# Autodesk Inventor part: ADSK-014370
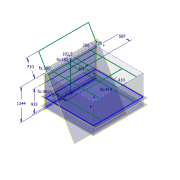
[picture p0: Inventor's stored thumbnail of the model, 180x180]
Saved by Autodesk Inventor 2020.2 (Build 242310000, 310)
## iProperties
Created: 2019-10
Part Number: ADSK-014370
Material: 1.0501 C35
Document SubType Name: Modeling
Designer: lutzd
Mass: 4.35255e+07 g
Surface Area: 194822 cm^2
Volume: 5.55173e+06 cm^3
Density: 7.84 g/cm^3
Appearance: Klar
VLDS_Profile: Default Part
VLDS_TimeStamp: 2016-07-29
VLDS_FailCnt: 0
VLDS_AcceptCnt: 0
Dimensions: 2170x1230x2080 mm
Mass: 43525,548 kg
DocNumber: ADSK-014370
Folder: 01 - Themengebiete\Simplification\01 - Packaging machine\Parts\
VDS_Category: 3D Komponenten
VDS_NumSchm: Autodesk
VLT_Material: 1.0501 C35
Title: skeleton
Author: lutzd
Revision Number: -
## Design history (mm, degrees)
sketch "Skizze1"
  geometry: L1 (-1040, -1085)-(1040, -1085); L2 (1040, -1085)-(1040, 1085); L3 (1040, 1085)-(-1040, 1085); L4 (-1040, 1085)-(-1040, -1085); L5 (-1040, -1085)-(1040, 1085); L6 (1040, -1085)-(-1040, 1085); 1 further point
  constraints: 12 end point, 2 midpoint, 2 parallel, 1 horizontal, 1 perpendicular
  dimensions: "d0" = 2080 distance of L3.end L2.end; "d1" = 2170 distance of L2.end L1.end
extrude "Extrusion1" new body sketch "Skizze1" distance "d2" = 1230; taper "d3" = 0 deg
workplane "Arbeitsebene1"
sketch "Skizze2"
  geometry: L1 (1040, -1085)-(-1040, -1085) reference; L2 (-1040, 1085)-(1040, 1085) reference; L3 (1040, -704)-(-1040, -704); L4 (1040, 704)-(-1040, 704); L5 (1040, 1085)-(1040, -1085) reference; L6 (-1040, -1085)-(-1040, 1085) reference; 1 further point
  constraints: 4 end point, 4 vertical alignment, 2 horizontal
  dimensions: "d5" = 381 distance between parallel lines of L2 L4; "d6" = 381 distance between parallel lines of L1 L3 (= d5)
sketch "Skizze3"
  geometry: L1 (-970, -805)-(1040, -805); L2 (-970, 805)-(1040, 805); L3 (1040, 1085)-(-1040, 1085) reference; L4 (-1040, 1085)-(-1040, -1085) reference; L5 (-1040, -1085)-(1040, -1085) reference; L6 (1040, -1085)-(1040, 1085) reference; L7 (-970, 1085)-(-970, -1085); L8 (-970, 0)-(1040, 0); L9 (-460, -805)-(-460, 0); L10 (-460, 0)-(-460, 805); L11 (-970, 182.5)-(-460, 182.5); L12 (-970, -182.5)-(-460, -182.5); L13 (1040, 182.5)-(630, 182.5); L14 (1040, -182.5)-(630, -182.5); L15 (405, -805)-(405, 0); L16 (405, 0)-(405, 805); 1 further point
  constraints: 24 end point, 20 point on line, 4 horizontal, 4 perpendicular, 2 collinear, 2 midpoint, 1 vertical
  dimensions: "d7" = 280 distance between parallel lines of L3 L2; "d8" = 280 distance between parallel lines of L5 L1 (= d7); "d9" = 70 distance between parallel lines of L4 L7; "d10" = 510 distance between parallel lines of L7 L10; "d11" = 182.5 distance between parallel lines of L8 L11; "d12" = 182.5 distance between parallel lines of L8 L12 (= d11); "d13" = 410 distance of L13.start L13.end; "d14" = 410 distance of L14.start L14.end (= d13); "d15" = 865 distance between parallel lines of L9 L15
workplane "Arbeitsebene3"
sketch "Skizze4"
  geometry: L1 (0, 2170)-(0, 0) reference; L2 (1344, 2170)-(1344, 0); 1 further point
  constraints: 2 end point, 2 horizontal alignment, 1 vertical
  dimensions: "d16" = 1344 distance between parallel lines of L1 L2
workplane "Arbeitsebene2"
sketch "Skizze5"
  geometry: L1 (0, 0)-(2170, 0) reference; L2 (2170, 0)-(2170, 710); L3 (2170, 710)-(0, 710); L4 (0, 710)-(0, 0); 1 further point
  constraints: 6 end point, 2 perpendicular, 1 vertical
  dimensions: "d18" = 710 distance of L1.end L2.end
sketch "Skizze6"
  geometry: L1 (0, 1085)-(1230, 1085); L2 (935, 2170)-(935, 1085); L3 (935, 1085)-(935, 0); L4 (0, 2170)-(0, 0) reference; 2 further points
  constraints: 6 end point, 2 horizontal alignment, 2 point on line, 1 horizontal, 1 perpendicular, 1 vertical alignment
  dimensions: "d20" = 935 distance between parallel lines of L4 L3
workplane "Arbeitsebene4"
node "Volumenkörper1"
feature "䁛"
other parameters: "d17" = 30 deg, "d21" = -35
